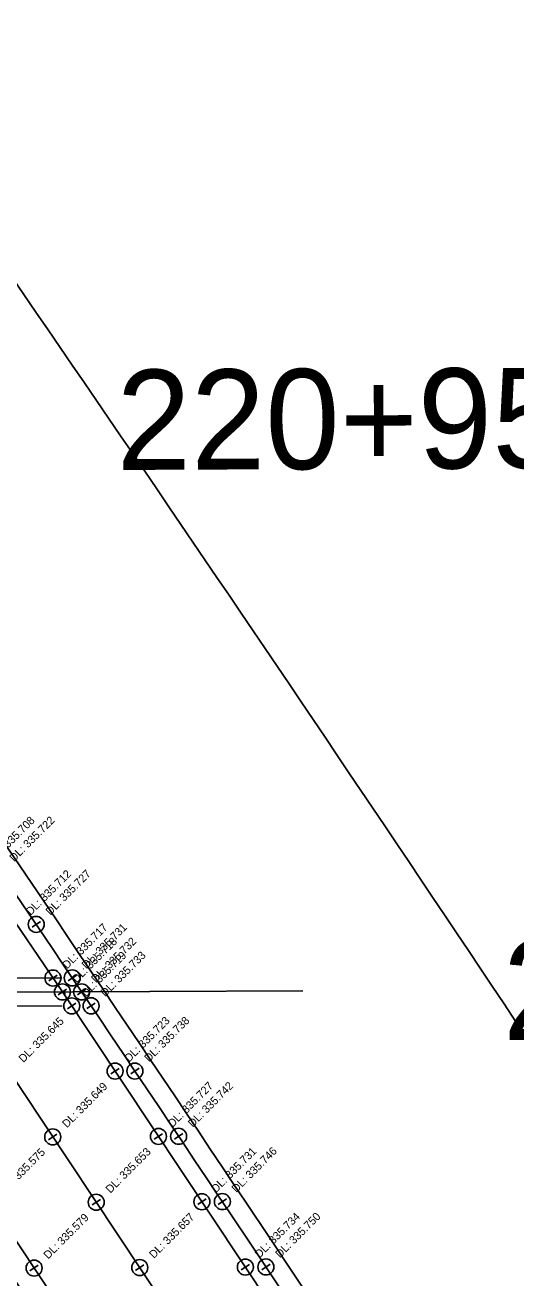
# Model space of a CAD drawing. Extents: x 1524497 to 1524592, y 1103688 to 1103812.
# Drawn here: x 1524542.12 to 1524554.39, y 1103749.84 to 1103781.14 of the extents above; entities that cross this region are included whole.
import ezdxf

# ---------------------------------------------------------------- set-up
doc = ezdxf.new("R2010")
doc.units = 0
doc.layers.add('Level 1', color=7, linetype='Continuous')

msp = doc.modelspace()

# ---------------------------------------------------------------- linework, layer by layer
at = {"layer": 'Level 1'}
for p, q in [((1524533.362, 1103771.225), (1524543.057, 1103756.984)), ((1524542.504, 1103758.744), (1524542.296, 1103758.604)), ((1524543.043, 1103757.334), (1524531.008, 1103757.279)), ((1524542.716, 1103757.263), (1524542.922, 1103757.404)), ((1524543.406, 1103757.405), (1524543.199, 1103757.266)), ((1524549.062, 1103757.012), (1524524.992, 1103756.901)), ((1524542.953, 1103756.914), (1524543.16, 1103757.055)), ((1524542.953, 1103756.915), (1524543.161, 1103757.054)), ((1524543.641, 1103757.056), (1524543.434, 1103756.917)), ((1524543.641, 1103757.056), (1524543.434, 1103756.917)), ((1524537.761, 1103756.96), (1524549.14, 1103739.912)), ((1524540.409, 1103756.972), (1524551.767, 1103739.924)), ((1524543.057, 1103756.984), (1524554.394, 1103739.936)), ((1524543.185, 1103756.566), (1524543.393, 1103756.705)), ((1524543.876, 1103756.708), (1524543.669, 1103756.568)), ((1524543.047, 1103756.634), (1524531.012, 1103756.579)), ((1524544.268, 1103754.937), (1524544.476, 1103755.075)), ((1524544.971, 1103755.078), (1524544.764, 1103754.939)), ((1524542.709, 1103753.294), (1524542.917, 1103753.432)), ((1524545.353, 1103753.306), (1524545.561, 1103753.444)), ((1524546.065, 1103753.447), (1524545.857, 1103753.308)), ((1524543.796, 1103751.662), (1524544.005, 1103751.8)), ((1524546.438, 1103751.674), (1524546.646, 1103751.813)), ((1524547.156, 1103751.815), (1524546.949, 1103751.676)), ((1524542.245, 1103750.016), (1524542.453, 1103750.155)), ((1524544.885, 1103750.029), (1524545.093, 1103750.167)), ((1524547.524, 1103750.041), (1524547.732, 1103750.179)), ((1524548.246, 1103750.182), (1524548.038, 1103750.043))]:
    msp.add_line(p, q, dxfattribs=at)
msp.add_lwpolyline([(1524543.117, 1103756.894), (1524543.109, 1103757.019), (1524543.057, 1103756.984)], dxfattribs=at)
for centre in [(1524542.4, 1103758.674), (1524542.819, 1103757.333), (1524543.302, 1103757.336), (1524543.057, 1103756.984), (1524543.057, 1103756.984), (1524543.537, 1103756.987), (1524543.537, 1103756.987), (1524543.289, 1103756.636), (1524543.772, 1103756.638), (1524544.372, 1103755.006), (1524544.867, 1103755.008), (1524542.813, 1103753.363), (1524545.457, 1103753.375), (1524545.961, 1103753.378), (1524543.9, 1103751.731), (1524546.542, 1103751.743), (1524547.053, 1103751.746), (1524542.349, 1103750.086), (1524544.989, 1103750.098), (1524547.628, 1103750.11), (1524548.142, 1103750.113)]:
    msp.add_circle(centre, 0.2, dxfattribs=at)
for radius, start, end in [(1750, 33.735131, 35.977852), (1750, 33.735131, 35.977852), (1750, 33.735131, 35.977852), (1750, 33.735131, 35.977852), (1750, 33.735131, 35.977852), (1750, 33.735131, 35.977852), (1750, 33.735131, 35.977852), (1750, 33.735131, 35.977852), (1741.4, 33.735131, 35.977852), (1741.4, 33.735131, 35.977852), (1741.4, 33.735131, 35.977852), (1741.4, 33.735131, 35.977852), (1741.4, 33.735131, 35.977852), (1741.4, 33.735131, 35.977852), (1741.4, 33.735131, 35.977852), (1741.4, 33.735131, 35.977852), (1741.88, 33.735131, 35.977852), (1741.88, 33.735131, 35.977852), (1741.88, 33.735131, 35.977852), (1741.88, 33.735131, 35.977852), (1741.88, 33.735131, 35.977852), (1741.88, 33.735131, 35.977852), (1741.88, 33.735131, 35.977852), (1741.88, 33.735131, 35.977852), (1736, 33.735131, 35.977852), (1736, 33.735131, 35.977852), (1736, 33.735131, 35.977852), (1736, 33.735131, 35.977852), (1736, 33.735131, 35.977852), (1736, 33.735131, 35.977852), (1736, 33.735131, 35.977852), (1736, 33.735131, 35.977852), (1750, 31.492411, 33.735131), (1750, 31.492411, 33.735131), (1750, 31.492411, 33.735131), (1750, 31.492411, 33.735131), (1750, 31.492411, 33.735131), (1750, 31.492411, 33.735131), (1750, 31.492411, 33.735131), (1750, 31.492411, 33.735131), (1741.88, 31.492411, 33.735131), (1741.88, 31.492411, 33.735131), (1741.88, 31.492411, 33.735131), (1741.88, 31.492411, 33.735131), (1741.88, 31.492411, 33.735131), (1741.88, 31.492411, 33.735131), (1741.88, 31.492411, 33.735131), (1741.88, 31.492411, 33.735131), (1741.4, 31.492411, 33.735131), (1741.4, 31.492411, 33.735131), (1741.4, 31.492411, 33.735131), (1741.4, 31.492411, 33.735131), (1741.4, 31.492411, 33.735131), (1741.4, 31.492411, 33.735131), (1741.4, 31.492411, 33.735131), (1741.4, 31.492411, 33.735131)]:
    msp.add_arc((1523099.068, 1102784.371), radius, start, end, dxfattribs=at)

# ---------------------------------------------------------------- texts
for s, height, rotation, p in [('220+95.799', 2.5, 0.265, (1524544.414, 1103770.026)), ('DL: 335.708', 0.2, 45, (1524541.351, 1103760.221)), ('DL: 335.722', 0.2, 45, (1524541.85, 1103760.223)), ('DL: 335.712', 0.2, 45, (1524542.262, 1103758.884)), ('DL: 335.727', 0.2, 45, (1524542.753, 1103758.886)), ('DL: 335.717', 0.2, 45, (1524543.173, 1103757.545)), ('DL: 335.731', 0.2, 45, (1524543.656, 1103757.548)), ('DL: 335.718', 0.2, 45, (1524543.41, 1103757.197)), ('DL: 335.718', 0.2, 45, (1524543.41, 1103757.197)), ('DL: 335.732', 0.2, 45, (1524543.891, 1103757.199)), ('DL: 335.732', 0.2, 45, (1524543.891, 1103757.199)), ('221+13.188', 2.5, 0.265, (1524554.068, 1103755.785)), ('DL: 335.719', 0.2, 45, (1524543.642, 1103756.848)), ('DL: 335.733', 0.2, 45, (1524544.126, 1103756.85)), ('DL: 335.645', 0.2, 45, (1524542.08, 1103755.206)), ('DL: 335.723', 0.2, 45, (1524544.726, 1103755.218)), ('DL: 335.738', 0.2, 45, (1524545.221, 1103755.22)), ('DL: 335.649', 0.2, 45, (1524543.167, 1103753.575)), ('DL: 335.727', 0.2, 45, (1524545.81, 1103753.587)), ('DL: 335.742', 0.2, 45, (1524546.314, 1103753.59)), ('DL: 335.575', 0.2, 45, (1524541.612, 1103751.931)), ('DL: 335.653', 0.2, 45, (1524544.254, 1103751.943)), ('DL: 335.731', 0.2, 45, (1524546.896, 1103751.955)), ('DL: 335.746', 0.2, 45, (1524547.406, 1103751.958)), ('DL: 335.579', 0.2, 45, (1524542.702, 1103750.298)), ('DL: 335.657', 0.2, 45, (1524545.342, 1103750.31)), ('DL: 335.734', 0.2, 45, (1524547.982, 1103750.322)), ('DL: 335.750', 0.2, 45, (1524548.496, 1103750.325))]:
    msp.add_text(s, height=height, rotation=rotation, dxfattribs=at).set_placement(p)

doc.saveas('drawing.dxf')
